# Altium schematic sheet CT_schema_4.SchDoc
size 287 x 163 mm
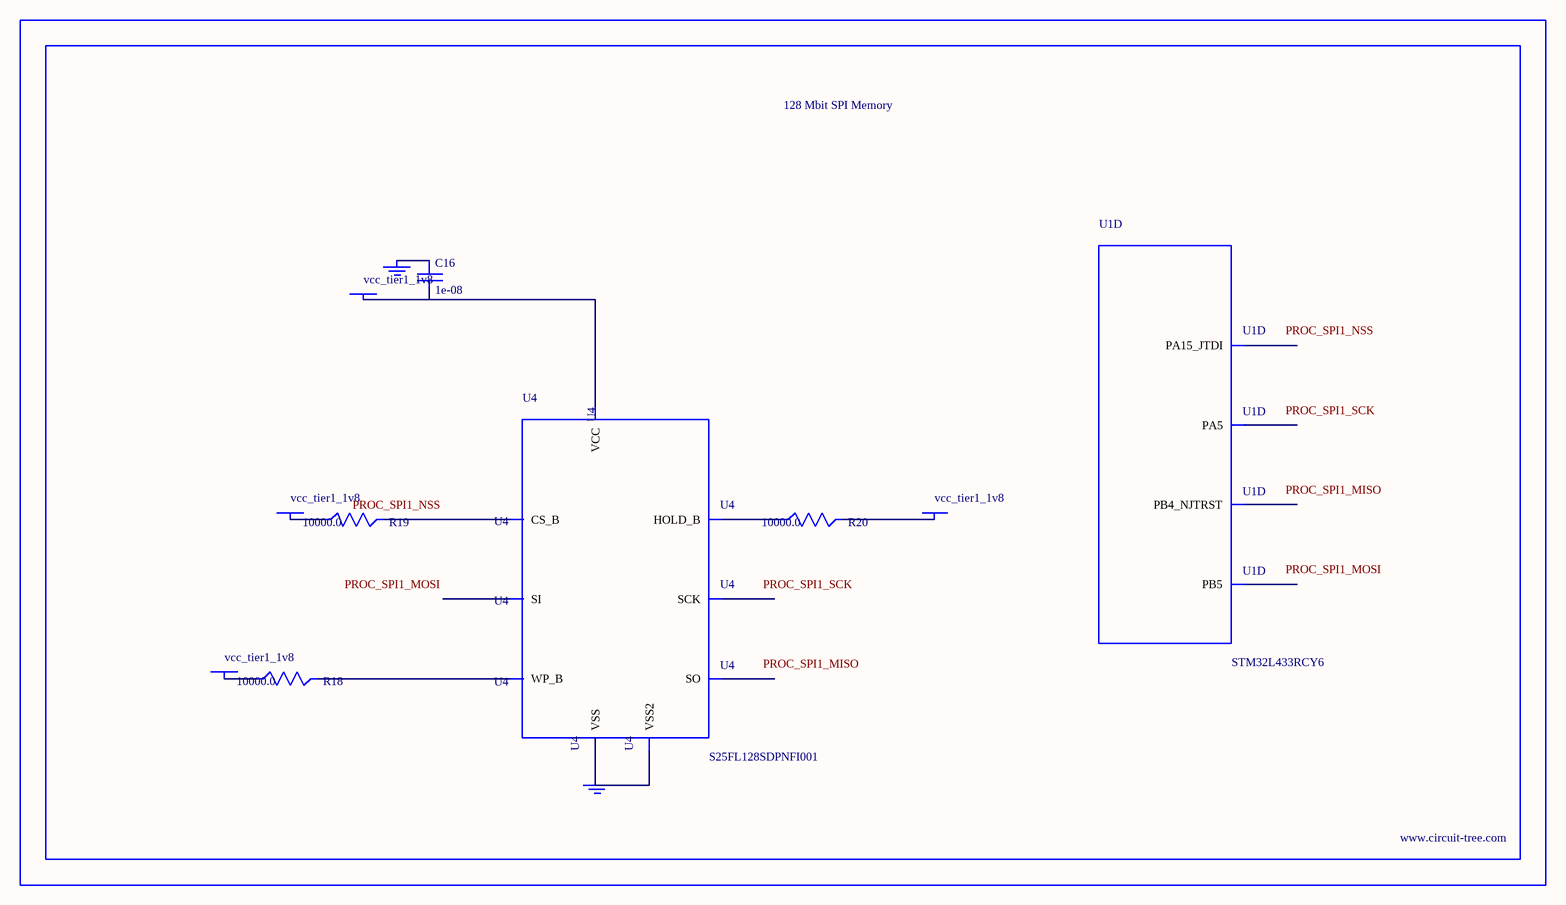
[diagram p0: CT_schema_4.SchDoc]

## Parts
BORDER3  (no value)
C16  1e-08  [C0402]
GND_INSTANCE_3_0  (no value)
GND_INSTANCE_3_1  (no value)
POWER_INSTANCE_3_0  vcc_tier1_1v8
POWER_INSTANCE_3_1  vcc_tier1_1v8
POWER_INSTANCE_3_2  vcc_tier1_1v8
POWER_INSTANCE_3_3  vcc_tier1_1v8
R18  10000.0  [R0603]
R19  10000.0  [R0603]
R20  10000.0  [R0603]
U1  STM32L433RCY6  [WLCSP64]  (part D of 8)
U4  S25FL128SDPNFI001  [WNG008]

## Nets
NetC16_1: C16.1 GND_INSTANCE_3_0.0(GND)
NetC16_2: C16.2 POWER_INSTANCE_3_3.0(PWR) U4.8(VCC)
NetGND_INSTANCE_3_1_0: GND_INSTANCE_3_1.0(GND) U4.4(VSS) U4.PAD(VSS2)
NetPOWER_INSTANCE_3_0_0: POWER_INSTANCE_3_0.0(PWR) R19.1
NetPOWER_INSTANCE_3_1_0: POWER_INSTANCE_3_1.0(PWR) R18.1
NetPOWER_INSTANCE_3_2_0: POWER_INSTANCE_3_2.0(PWR) R20.2
NetR18_2: R18.2 U4.3(WP_B)
NetR19_2: R19.2 U4.1(CS_B)
NetR20_1: R20.1 U4.7(HOLD_B)

Not connected (* = marked no-connect by the designer): U1 A2(PA15_JTDI) B4(PB4_NJTRST) C4(PB5) F5(PA5); U4 2(SO) 5(SI) 6(SCK)

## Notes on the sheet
- Labels drawn without touching a wire or pin: PROC_SPI1_MISO, PROC_SPI1_MOSI, PROC_SPI1_NSS, PROC_SPI1_SCK

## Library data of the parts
BORDER3 = BORDER_PAGE3
C16 = C0402C103K3RAC
GND_INSTANCE_3_0 GND_INSTANCE_3_1 = GND
POWER_INSTANCE_3_0-POWER_INSTANCE_3_3 = PWR
R18-R20 = RC0603JR-0710KL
